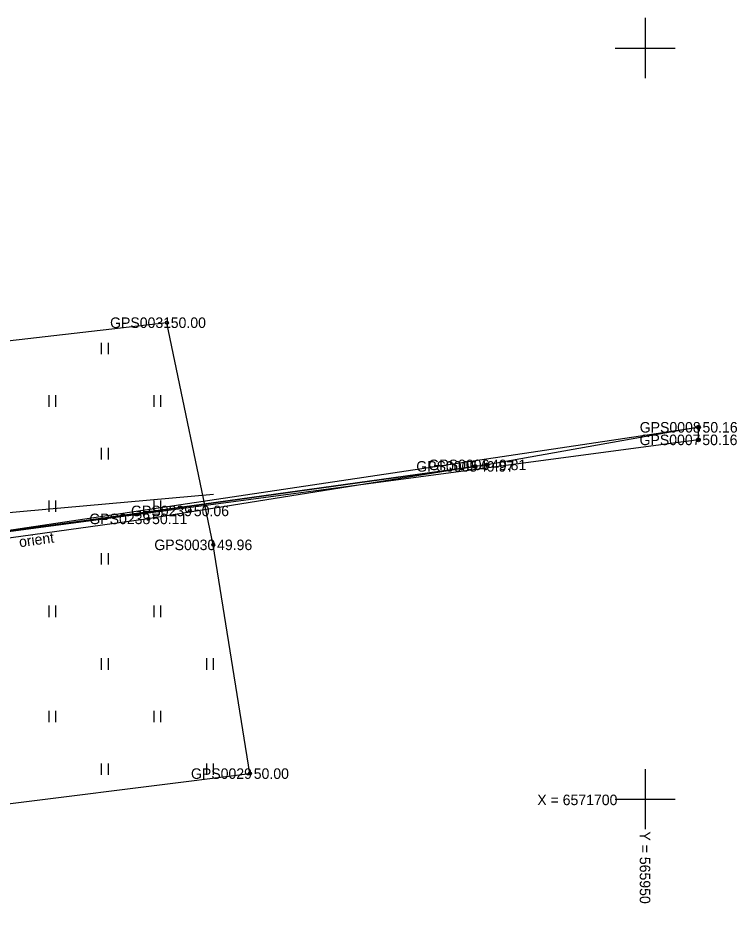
# Model space of a CAD drawing. Extents: x 563121 to 567545, y 6570841 to 6581299.
# Drawn here: x 565908.2 to 565956.1, y 6571692.2 to 6571752 of the extents above; entities that cross this region are included whole.
import ezdxf

# ---------------------------------------------------------------- set-up
doc = ezdxf.new("R2010")
doc.units = 0
for name, color, linetype in [('HALJASTUS', 7, 'Continuous'), ('KORGUS-EH2000', 7, 'Continuous'), ('MOOTKORG-EH2000', 7, 'Continuous'), ('MOOTMPUNKT', 7, 'Continuous'), ('MOOTNR', 7, 'Continuous'), ('MOOTPIIR', 7, 'Continuous'), ('MPKAABEL', 7, 'Continuous'), ('POST', 7, 'Continuous'), ('VORK', 7, 'Continuous')]:
    doc.layers.add(name, color=color, linetype=linetype)

msp = doc.modelspace()

# ---------------------------------------------------------------- linework, layer by layer
at = {"layer": 'HALJASTUS'}
for p, q in [((565913.772, 6571730.381), (565913.772, 6571729.619)), ((565914.228, 6571730.381), (565914.228, 6571729.619)), ((565910.272, 6571726.881), (565910.272, 6571726.119)), ((565910.728, 6571726.881), (565910.728, 6571726.119)), ((565917.272, 6571726.881), (565917.272, 6571726.119)), ((565917.728, 6571726.881), (565917.728, 6571726.119)), ((565913.772, 6571723.381), (565913.772, 6571722.619)), ((565914.228, 6571723.381), (565914.228, 6571722.619)), ((565910.272, 6571719.881), (565910.272, 6571719.119)), ((565910.728, 6571719.881), (565910.728, 6571719.119)), ((565917.272, 6571719.881), (565917.272, 6571719.119)), ((565917.728, 6571719.881), (565917.728, 6571719.119)), ((565913.772, 6571716.381), (565913.772, 6571715.619)), ((565914.228, 6571716.381), (565914.228, 6571715.619)), ((565910.272, 6571712.881), (565910.272, 6571712.119)), ((565910.728, 6571712.881), (565910.728, 6571712.119)), ((565917.272, 6571712.881), (565917.272, 6571712.119)), ((565917.728, 6571712.881), (565917.728, 6571712.119)), ((565913.772, 6571709.381), (565913.772, 6571708.619)), ((565914.228, 6571709.381), (565914.228, 6571708.619)), ((565920.772, 6571709.381), (565920.772, 6571708.619)), ((565921.228, 6571709.381), (565921.228, 6571708.619)), ((565910.272, 6571705.881), (565910.272, 6571705.119)), ((565910.728, 6571705.881), (565910.728, 6571705.119)), ((565917.272, 6571705.881), (565917.272, 6571705.119)), ((565917.728, 6571705.881), (565917.728, 6571705.119)), ((565913.772, 6571702.381), (565913.772, 6571701.619)), ((565914.228, 6571702.381), (565914.228, 6571701.619)), ((565920.772, 6571702.381), (565920.772, 6571701.619)), ((565921.228, 6571702.381), (565921.228, 6571701.619))]:
    msp.add_line(p, q, dxfattribs=at)
at = {"layer": 'KORGUS-EH2000'}
for centre in [(565918.14, 6571731.716), (565921.225, 6571716.927), (565923.667, 6571701.7)]:
    msp.add_circle(centre, 0.1, dxfattribs=at)
at = {"layer": 'MOOTMPUNKT'}
for centre in [(565918.14, 6571731.716), (565953.549, 6571724.752), (565953.537, 6571723.916), (565939.474, 6571722.251), (565938.668, 6571722.15), (565916.898, 6571718.657), (565919.677, 6571719.187), (565921.225, 6571716.927), (565923.667, 6571701.7)]:
    msp.add_circle(centre, 0.1, dxfattribs=at)
at = {"layer": 'MOOTPIIR'}
msp.add_lwpolyline([(565847.666, 6571692.22), (565872.552, 6571695.122), (565896.74, 6571698.337), (565923.667, 6571701.7), (565921.225, 6571716.927), (565918.14, 6571731.716), (565901.33, 6571729.772), (565893.791, 6571728.537), (565867.263, 6571724.668), (565843.294, 6571721.486)], dxfattribs=at)
at = {"layer": 'MPKAABEL'}
for points in [[(565953.537, 6571723.916), (565953.549, 6571724.752), (565939.474, 6571722.251), (565938.668, 6571722.15), (565916.898, 6571718.657), (565903.915, 6571716.853), (565901.066, 6571716.93)], [(565921.258, 6571720.287), (565905.596, 6571718.882), (565902.551, 6571719.869), (565901.417, 6571719.812)]]:
    msp.add_lwpolyline(points, dxfattribs=at)
at = {"layer": 'POST'}
for points in [[(565953.537, 6571723.916), (565901.066, 6571716.93), (565953.549, 6571724.752)], [(565939.474, 6571722.251), (565901.066, 6571716.93), (565938.668, 6571722.15)]]:
    msp.add_lwpolyline(points, dxfattribs=at)
for centre, radius in [((565953.549, 6571724.752), 0.125), ((565953.549, 6571724.752), 0.105), ((565953.549, 6571724.752), 0.0851), ((565953.549, 6571724.752), 0.0651), ((565953.549, 6571724.752), 0.0451), ((565953.549, 6571724.752), 0.0251), ((565953.549, 6571724.752), 0.00511), ((565953.537, 6571723.916), 0.125), ((565953.537, 6571723.916), 0.105), ((565953.537, 6571723.916), 0.0851), ((565953.537, 6571723.916), 0.0651), ((565953.537, 6571723.916), 0.0451), ((565953.537, 6571723.916), 0.0251), ((565953.537, 6571723.916), 0.00511), ((565939.474, 6571722.251), 0.125), ((565939.474, 6571722.251), 0.105), ((565939.474, 6571722.251), 0.0851), ((565938.668, 6571722.15), 0.125), ((565938.668, 6571722.15), 0.105), ((565938.668, 6571722.15), 0.0851), ((565938.668, 6571722.15), 0.0651), ((565938.668, 6571722.15), 0.0451), ((565938.668, 6571722.15), 0.0251), ((565938.668, 6571722.15), 0.00511), ((565939.474, 6571722.251), 0.0651), ((565939.474, 6571722.251), 0.0451), ((565939.474, 6571722.251), 0.0251), ((565939.474, 6571722.251), 0.00511)]:
    msp.add_circle(centre, radius, dxfattribs=at)
at = {"layer": 'VORK'}
for p, q in [((565950, 6571752), (565950, 6571748)), ((565948, 6571750), (565952, 6571750)), ((565950, 6571702), (565950, 6571698)), ((565948, 6571700), (565952, 6571700))]:
    msp.add_line(p, q, dxfattribs=at)

# ---------------------------------------------------------------- texts
at = {"layer": 'KORGUS-EH2000'}
for s, p in [(' 50.00', (565918.14, 6571731.366)), (' 49.96', (565921.225, 6571716.577)), (' 50.00', (565923.667, 6571701.35))]:
    msp.add_text(s, height=0.7, dxfattribs=at).set_placement(p)
at = {"layer": 'MOOTKORG-EH2000'}
for s, p in [(' 50.00', (565918.14, 6571731.366)), (' 50.16', (565953.549, 6571724.402)), (' 50.16', (565953.537, 6571723.566)), (' 49.97', (565938.668, 6571721.8)), (' 49.81', (565939.474, 6571721.901)), (' 50.06', (565919.677, 6571718.837)), (' 50.11', (565916.898, 6571718.307)), (' 49.96', (565921.225, 6571716.577)), (' 50.00', (565923.667, 6571701.35))]:
    msp.add_text(s, height=0.7, dxfattribs=at).set_placement(p)
at = {"layer": 'MOOTNR'}
for s, p in [('GPS0031 ', (565914.36, 6571731.366)), ('GPS0008 ', (565949.63, 6571724.402)), ('GPS0007 ', (565949.617, 6571723.566)), ('GPS0005 ', (565934.749, 6571721.8)), ('GPS0006 ', (565935.555, 6571721.901)), ('GPS0239 ', (565915.757, 6571718.837)), ('GPS0238 ', (565912.978, 6571718.307)), ('GPS0030 ', (565917.306, 6571716.577)), ('GPS0029 ', (565919.747, 6571701.35))]:
    msp.add_text(s, height=0.7, dxfattribs=at).set_placement(p)
at = {"layer": 'MPKAABEL'}
msp.add_text('orient', height=0.7, rotation=7.86652, dxfattribs=at).set_placement((565908.345, 6571716.766))
at = {"layer": 'VORK'}
msp.add_text('X = 6571700', height=0.7, dxfattribs=at).set_placement((565942.809, 6571699.601))
msp.add_text('Y = 565950 ', height=0.7, rotation=270, dxfattribs=at).set_placement((565949.633, 6571697.851))

doc.saveas('drawing.dxf')
